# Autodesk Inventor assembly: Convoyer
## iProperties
Created: 2001-12
Part Number: Convoyer
Document SubType Name: Assembly
Designer: Tobben
Control State: 0
Master: False
Checked Out: False
Shininess: 64.0
Length Units: 11269
Angle Units: 11279
Time Units: 11290
Mass Units: 11283
Length Display Precision: 3
Angle Display Precision: 2
Density: 0.0
Volumn: 0.0
Area: 0.0
PropertySet Name: Model Information
Author: Tobben
